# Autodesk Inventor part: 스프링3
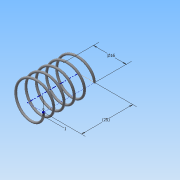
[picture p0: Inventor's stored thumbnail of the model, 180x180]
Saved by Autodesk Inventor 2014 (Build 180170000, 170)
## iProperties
Created: 2015-06
Part Number: 스프링3
Material: 강철, 연강
Document SubType Name: Modeling
Designer: Administrator
Density: 7.86 g/cm^3
Appearance: 강철
Mass: 1.53479 g
Surface Area: 7.89194 cm^2
Volume: 0.195266 cm^3
Author: Administrator
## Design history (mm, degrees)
sketch "스케치1"
  geometry: L1 (0, 0)-(8, 0); L2 (8, 0)-(8, 21.5); L3 (8, 21.5)-(0, 21.5); L4 (0, 21.5)-(0, 0); C1 r 0.5 at (8, 0)
  constraints: 8 end point, 2 parallel, 1 centre point, 1 coincident, 1 horizontal, 1 perpendicular
  dimensions: "d0" = 21.5 distance of L1.end L2.end (derived); "d1" = 16 diameter of L2 L4; "d2" = 1 diameter of C1
feature "코일1" sketch "스케치1" pitch "d3" = 10; turns "d5" = 5; dims "d4" = 21.5 (= d0), "d6" = 0, angle "d7" = 90 deg, angle "d8" = 90 deg, "d9" = 0, "d10" = 0
sketch "스케치2"
  geometry: L1 (-8.5, 0)-(-7.5, 0) reference; 1 further point
  constraints: 1 horizontal alignment
extrude "돌출1" cut sketch "스케치2" stored distance "d11" = 10; taper "d12" = 0 deg
node "작업 평면1"
sketch "스케치3"
  geometry: L1 (-7.5, 0)-(-8.5, 0) reference; 1 further point
  constraints: 1 horizontal alignment
extrude "돌출2" cut sketch "스케치3" stored distance "d14" = 10; taper "d15" = 0 deg
node "솔리드1"
node "절단 모서리 투영1"
node "절단 모서리 투영2"
other parameters: "d13" = 21.5 (= d0)
